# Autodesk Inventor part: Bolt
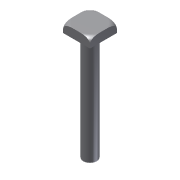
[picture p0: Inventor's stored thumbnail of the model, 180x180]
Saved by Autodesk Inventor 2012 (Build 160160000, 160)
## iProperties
Created: 2009-04
Part Number: Bolt
Document SubType Name: Modeling
Designer: Sham
Density: 1 g/cm^3
Mass: 15.4148 g
Surface Area: 54.8703 cm^2
Volume: 15.4148 cm^3
Material: Default
Author: Sham
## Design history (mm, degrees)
sketch "Sketch1"
  geometry: L1 (-12, 12)-(12, 12); L2 (12, 12)-(12, -12); L3 (12, -12)-(-12, -12); L4 (-12, -12)-(-12, 12); 1 further point
  constraints: 8 end point, 2 parallel, 2 perpendicular, 1 horizontal, 1 other
  dimensions: "d0" = 24 distance of L1.start L1.end; "d1" = 12 distance from line of L2 point (0, 0); "d2" = 12 distance from line of L1 point (0, 0)
extrude "Extrusion1" new body sketch "Sketch1" distance "d3" = 8; taper "d4" = 0 deg
sketch "Sketch2"
  geometry: C1 r 6 at (0, 0)
  constraints: 1 centre point
  dimensions: "d5" = 12 diameter of C1
extrude "Extrusion2" join sketch "Sketch2" distance "d6" = 96; taper "d7" = 0 deg
workpoint "Work Point1"
workplane "Work Plane1"
sketch "Sketch3"
  geometry: L1 (33.941, 5)-(33.941, 6); L2 (28.941, 0)-(28.405, 0); L3 (16.971, 125.007)-(16.971, -22.043) reference; A1 r 5 centre (28.941, 5) between (28.941, 0) and (33.941, 5); 1 further point
  constraints: 4 end point, 2 point on circle, 2 point on line, 2 tangent, 1 centre point, 1 perpendicular
  dimensions: "d10" = 5 radius of A1
revolve "Revolution1" sketch "Sketch3" stored, may be unused: angle "d12" = 90 deg
body "Solid1"
other parameters: "d11" = 90 deg
